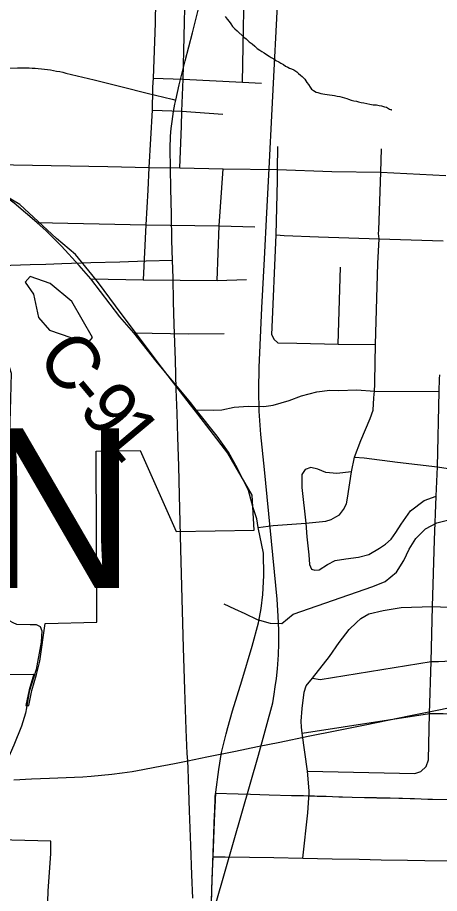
# Model space of a CAD drawing. Extents: x -6.1 to 38, y -7.7 to 22.
# Drawn here: x 5.52 to 5.97, y 16.475 to 17.41 of the extents above; entities that cross this region are included whole.
import ezdxf

# ---------------------------------------------------------------- set-up
doc = ezdxf.new("R2010")
doc.units = 0
for name, color, linetype in [('GM_X_City_Street', 7, 'Continuous'), ('GM_X_Corporation', 7, 'Continuous'), ('GM_X_County_Road', 7, 'Continuous'), ('GM_X_County_Road_Text', 7, 'Continuous'), ('GM_X_Minor_Lake', 7, 'Continuous'), ('GM_X_Minor_River', 7, 'Continuous'), ('GM_X_Rail_Line', 7, 'Continuous'), ('GM_X_Township_Road', 7, 'Continuous'), ('GM_X_Township_Text', 7, 'Continuous'), ('GM_X_US_Route', 7, 'Continuous')]:
    doc.layers.add(name, color=color, linetype=linetype)

msp = doc.modelspace()

# ---------------------------------------------------------------- linework, layer by layer
at = {"layer": 'GM_X_City_Street'}
for p, q in [((5.90593, 17.17394), (5.97422, 17.17178)), ((5.86205, 17.06131), (5.8648, 17.14378))]:
    msp.add_line(p, q, dxfattribs=at)
for points in [[(5.6952, 17.31034), (5.69669, 17.34437), (5.6988, 17.43612), (5.70028, 17.51838), (5.70175, 17.57512)], [(5.75997, 17.34142), (5.7625, 17.47557), (5.76356, 17.5226), (5.76419, 17.5728)], [(5.66809, 17.50632), (5.66822, 17.50045), (5.66695, 17.40448), (5.66463, 17.34543), (5.664, 17.33593), (5.66396, 17.33371)], [(5.66463, 17.34543), (5.69669, 17.34437), (5.75997, 17.34142), (5.78022, 17.34036)], [(5.66396, 17.33371), (5.66356, 17.31151), (5.6602, 17.25029), (5.65894, 17.22583), (5.65683, 17.18892), (5.65388, 17.13007)], [(5.66356, 17.31151), (5.6952, 17.31034), (5.73909, 17.30704)], [(5.6931, 17.24988), (5.69479, 17.29417), (5.6952, 17.31034)], [(5.79119, 17.07122), (5.79604, 17.17816), (5.7973, 17.23616), (5.7973, 17.24798), (5.79772, 17.27245)], [(5.90543, 17.18317), (5.90773, 17.24496), (5.90849, 17.27012)], [(5.73318, 17.12944), (5.73529, 17.18765), (5.7393, 17.24882)], [(5.54061, 17.19124), (5.65683, 17.18892), (5.73529, 17.18765), (5.77325, 17.1866)], [(5.90135, 17.02145), (5.90213, 17.06089), (5.90466, 17.14758), (5.90593, 17.17394), (5.9053, 17.17964), (5.90543, 17.18317)], [(5.79604, 17.17816), (5.80447, 17.17732), (5.84118, 17.17605), (5.90593, 17.17394)], [(5.59798, 17.13113), (5.65388, 17.13007), (5.73318, 17.12944), (5.7644, 17.13049)], [(5.64396, 17.07355), (5.70281, 17.07228), (5.74035, 17.0727)], [(5.79119, 17.07122), (5.79351, 17.06679), (5.79772, 17.06278), (5.81819, 17.06258), (5.86205, 17.06131), (5.90213, 17.06089)], [(5.71061, 16.99128), (5.72939, 16.99086), (5.73803, 16.99138), (5.75132, 16.99402), (5.76608, 16.99508), (5.78276, 16.99463), (5.79262, 16.99608), (5.80993, 17.00113), (5.82303, 17.00605), (5.83928, 17.01048), (5.8532, 17.01217), (5.86238, 17.01196), (5.88209, 17.01259), (5.90087, 17.01132), (5.96984, 17.01069)], [(5.87957, 16.94072), (5.88631, 16.95859), (5.89644, 16.98201), (5.8996, 16.99086), (5.90023, 17.00415), (5.90087, 17.01132), (5.90129, 17.01849), (5.90135, 17.02145)], [(5.7769, 16.86559), (5.79291, 16.86772), (5.82752, 16.87028), (5.84897, 16.87232), (5.85482, 16.87393), (5.85958, 16.87696), (5.86348, 16.87913), (5.86796, 16.8849), (5.87099, 16.89097), (5.87215, 16.89674), (5.87641, 16.92511), (5.87957, 16.94072), (5.8899, 16.94003), (5.92555, 16.93518), (5.96815, 16.93033), (5.99346, 16.92653), (6.01392, 16.92379), (6.02341, 16.92273), (6.03565, 16.92168)], [(5.87641, 16.92511), (5.86079, 16.92337), (5.84885, 16.92447), (5.84033, 16.92801), (5.83288, 16.92959), (5.82682, 16.92767), (5.82346, 16.92231), (5.82346, 16.90839), (5.82752, 16.87028), (5.82873, 16.85566), (5.83084, 16.83647), (5.83158, 16.82598), (5.83379, 16.82087), (5.83735, 16.81982), (5.84202, 16.82044), (5.85067, 16.82592), (5.85915, 16.83032), (5.87041, 16.83205), (5.88398, 16.83393), (5.89509, 16.83682), (5.90635, 16.84332), (5.91285, 16.84779), (5.91892, 16.85313), (5.92365, 16.86009), (5.92934, 16.86916), (5.93947, 16.8835), (5.95402, 16.89426), (5.96667, 16.8989)], [(5.83476, 16.7046), (5.85299, 16.72764), (5.86325, 16.74267), (5.87384, 16.75654), (5.88165, 16.76411), (5.88644, 16.76839), (5.89502, 16.77318), (5.9104, 16.77697), (5.92956, 16.77999), (5.96284, 16.781), (6.00646, 16.77949), (6.0187, 16.77893)], [(5.83476, 16.7046), (5.84282, 16.70334), (5.96158, 16.7225), (5.9694, 16.7225), (6.00946, 16.7247), (6.02805, 16.72531), (6.13288, 16.72383)], [(5.82946, 16.60526), (5.82388, 16.64578), (5.82321, 16.65223), (5.82265, 16.65871), (5.82366, 16.67233), (5.82591, 16.68951), (5.82795, 16.69628), (5.83476, 16.7046)], [(5.82388, 16.64578), (5.95957, 16.66678), (5.97444, 16.66678), (6.01327, 16.66527)]]:
    msp.add_lwpolyline(points, dxfattribs=at)
at = {"layer": 'GM_X_Corporation'}
for points in [[(5.50677, 16.70867), (5.53716, 16.70898), (5.53213, 16.69201), (5.52887, 16.67551), (5.53191, 16.67555), (5.53505, 16.69142), (5.54006, 16.70833), (5.54351, 16.72274), (5.54936, 16.76281), (5.60458, 16.76434), (5.6037, 16.94714), (5.65067, 16.94789), (5.68927, 16.86134), (5.7726, 16.86263), (5.77032, 16.89994), (5.74442, 16.94494), (5.72537, 16.96963), (5.71231, 16.98661), (5.70443, 16.99676), (5.67014, 17.04135), (5.62434, 17.10243), (5.60636, 17.12675), (5.59919, 17.13567), (5.58177, 17.15732), (5.56164, 17.17432), (5.52233, 17.21064), (5.47136, 17.2404)], [(5.98064, 16.57447), (5.96284, 16.57495), (5.95795, 16.57512), (5.95091, 16.57528), (5.94353, 16.57557), (5.93898, 16.5756), (5.93086, 16.57586), (5.92705, 16.57593), (5.91752, 16.57624), (5.91512, 16.57625), (5.90376, 16.57657), (5.90319, 16.57658), (5.90189, 16.57662), (5.89127, 16.5767), (5.89046, 16.5767), (5.87723, 16.57719), (5.86669, 16.57758), (5.86274, 16.57762), (5.8492, 16.57803), (5.83965, 16.57831), (5.83699, 16.57839), (5.83397, 16.57847), (5.83039, 16.57857), (5.82512, 16.57876), (5.81222, 16.57906), (5.78836, 16.57971), (5.76873, 16.58025), (5.7555, 16.5806), (5.73074, 16.58129), (5.7306, 16.57773), (5.72999, 16.56207), (5.72986, 16.5588), (5.72785, 16.50714), (5.72709, 16.47831), (5.72702, 16.47565), (5.72589, 16.45274)], [(5.55226, 16.46594), (5.55266, 16.47692), (5.55533, 16.51714), (5.55542, 16.53037), (5.45844, 16.5328)]]:
    msp.add_lwpolyline(points, dxfattribs=at)
at = {"layer": 'GM_X_County_Road'}
msp.add_line((5.82946, 16.60526), (5.94418, 16.60274), dxfattribs=at)
for points in [[(5.68534, 17.15118), (5.68477, 17.17223), (5.68409, 17.20004), (5.68341, 17.22785), (5.68308, 17.24916), (5.68273, 17.27047), (5.68316, 17.28374), (5.684, 17.29169), (5.68485, 17.29912), (5.68637, 17.31012), (5.68798, 17.31789), (5.68901, 17.32221), (5.69254, 17.33826), (5.69888, 17.36397), (5.70273, 17.37906), (5.70658, 17.39415), (5.71329, 17.42112)], [(5.7044, 16.9989), (5.69944, 17.005), (5.68488, 17.0225), (5.66801, 17.04338), (5.64396, 17.07355), (5.62922, 17.09051), (5.59798, 17.13113), (5.58574, 17.14526), (5.56676, 17.16593), (5.55031, 17.18238), (5.54061, 17.19124), (5.51614, 17.21191), (5.49484, 17.22752), (5.47706, 17.23951), (5.45392, 17.25472), (5.442, 17.26098), (5.43529, 17.2653), (5.42186, 17.27321), (5.41299, 17.27849)], [(5.45392, 17.25472), (5.51551, 17.25304), (5.61633, 17.25114), (5.6602, 17.25029), (5.6931, 17.24988), (5.7393, 17.24882), (5.7973, 17.24798), (5.85552, 17.24591), (5.90773, 17.24496), (5.97716, 17.24175)], [(5.70152, 16.61628), (5.701, 16.62422), (5.69998, 16.64984), (5.69926, 16.67123), (5.69854, 16.69262), (5.69787, 16.71481), (5.69719, 16.737), (5.69644, 16.76326), (5.69567, 16.7895), (5.69499, 16.81588), (5.69432, 16.84226), (5.69351, 16.87126), (5.69271, 16.90025), (5.69195, 16.93107), (5.69119, 16.96189), (5.6903, 16.98754), (5.68941, 17.0132), (5.68843, 17.04425), (5.68782, 17.06326), (5.68721, 17.08227), (5.68654, 17.10705), (5.68586, 17.13181), (5.68534, 17.15118)], [(5.94418, 16.60274), (5.95049, 16.60501), (5.95604, 16.61005), (5.95855, 16.61736), (5.95957, 16.66678), (5.96158, 16.7225), (5.96284, 16.781), (5.96498, 16.85208), (5.96667, 16.8989), (5.96815, 16.93033), (5.96984, 17.01069), (5.97047, 17.0244), (5.97082, 17.02876)], [(5.74437, 16.65175), (5.74953, 16.6698), (5.75937, 16.70158), (5.77021, 16.73864), (5.77701, 16.76386), (5.78004, 16.77899), (5.7818, 16.79386), (5.78281, 16.81429), (5.78231, 16.83798), (5.7769, 16.86559), (5.77533, 16.87464), (5.7714, 16.88644), (5.76628, 16.90492), (5.75469, 16.92843), (5.74499, 16.94594), (5.73297, 16.96323), (5.71061, 16.99128), (5.7044, 16.9989)], [(5.73111, 16.57374), (5.73163, 16.58282), (5.73466, 16.60702), (5.7378, 16.62503), (5.74247, 16.6451), (5.74437, 16.65175)], [(5.707, 16.46973), (5.70607, 16.49462), (5.70495, 16.52567), (5.70428, 16.54426), (5.70362, 16.56284), (5.70277, 16.58538), (5.70192, 16.60791), (5.70152, 16.61628)], [(5.72684, 16.46381), (5.7276, 16.49053), (5.72886, 16.51374), (5.73037, 16.56063), (5.73111, 16.57374)]]:
    msp.add_lwpolyline(points, dxfattribs=at)
at = {"layer": 'GM_X_Minor_Lake'}
for points in [[(5.59507, 17.0625), (5.59996, 17.06859), (5.57785, 17.10687), (5.55467, 17.12617), (5.53345, 17.13371), (5.52818, 17.12763)], [(5.52818, 17.12763), (5.53694, 17.11474), (5.54234, 17.08971), (5.55414, 17.07645), (5.57688, 17.06853), (5.59507, 17.0625)]]:
    msp.add_lwpolyline(points, dxfattribs=at)
at = {"layer": 'GM_X_Minor_River'}
for points in [[(5.74138, 17.41133), (5.7437, 17.40871), (5.74565, 17.40609), (5.7476, 17.40346), (5.74954, 17.40083), (5.75187, 17.39821), (5.75419, 17.39597), (5.76152, 17.38926), (5.76384, 17.3874), (5.76731, 17.38442), (5.77039, 17.38219), (5.77309, 17.37958), (5.77579, 17.37735), (5.77848, 17.3755), (5.78079, 17.37402), (5.78309, 17.37254), (5.78578, 17.37069), (5.78847, 17.36921), (5.79077, 17.36773), (5.79346, 17.36626), (5.79577, 17.3644), (5.79884, 17.36293), (5.80114, 17.36145), (5.80383, 17.35998), (5.80613, 17.3585), (5.80843, 17.3574), (5.81035, 17.3563), (5.81226, 17.35557)], [(5.81226, 17.35557), (5.81494, 17.35448), (5.81802, 17.35225), (5.81995, 17.35038), (5.82188, 17.3489), (5.8238, 17.34741), (5.82651, 17.34442), (5.82885, 17.34104), (5.83041, 17.33879), (5.83237, 17.33578), (5.83354, 17.3339), (5.83584, 17.33242), (5.83854, 17.33057), (5.84044, 17.33022), (5.8435, 17.32913), (5.84807, 17.32846), (5.85035, 17.32812), (5.85835, 17.32712), (5.86102, 17.32641), (5.86406, 17.32608), (5.86636, 17.32536), (5.86903, 17.32465), (5.87132, 17.32393), (5.87323, 17.3232), (5.87591, 17.32211), (5.87896, 17.32141), (5.88162, 17.32107), (5.88392, 17.32035), (5.88659, 17.31964), (5.88963, 17.31932), (5.89268, 17.31861), (5.89611, 17.31791), (5.89954, 17.31721), (5.90297, 17.3169), (5.90602, 17.31619), (5.9083, 17.31585), (5.91174, 17.31477), (5.91365, 17.31443), (5.9171, 17.31259), (5.91901, 17.31186), (5.91939, 17.31187), (5.91901, 17.31186)], [(5.74025, 16.78404), (5.75161, 16.77877), (5.7626, 16.7735), (5.77585, 16.7671), (5.78948, 16.76335), (5.80196, 16.76301), (5.81403, 16.7729), (5.89904, 16.80236), (5.91226, 16.80771), (5.92433, 16.81798), (5.93223, 16.83013), (5.93787, 16.84228), (5.94502, 16.85368), (5.95557, 16.86394), (5.96766, 16.87043), (5.98164, 16.87426)]]:
    msp.add_lwpolyline(points, dxfattribs=at)
at = {"layer": 'GM_X_Rail_Line'}
msp.add_lwpolyline([(5.70525, 16.37213), (5.77707, 16.62218), (5.7924, 16.67838), (5.79376, 16.68741), (5.79503, 16.69527), (5.79629, 16.7044), (5.79736, 16.71449), (5.79842, 16.72963), (5.79891, 16.74167), (5.79881, 16.75594), (5.79803, 16.77098), (5.79697, 16.78884), (5.78338, 16.92754), (5.77979, 16.96491), (5.77785, 16.98976), (5.77736, 17.01277), (5.77775, 17.03664), (5.78076, 17.10012), (5.78367, 17.15244), (5.7859, 17.20165), (5.78843, 17.24921), (5.79173, 17.3125), (5.79842, 17.4447)], dxfattribs=at)
at = {"layer": 'GM_X_Township_Road'}
msp.add_line((5.83106, 16.58417), (5.82946, 16.60526), dxfattribs=at)
for points in [[(5.49627, 17.35586), (5.51992, 17.35657), (5.5255, 17.35665), (5.53214, 17.35654), (5.53546, 17.3564), (5.53873, 17.35619), (5.54204, 17.35594), (5.54531, 17.35562), (5.54862, 17.35525), (5.55189, 17.35482), (5.55517, 17.35433), (5.55844, 17.35379), (5.56165, 17.35318), (5.56492, 17.35253), (5.56815, 17.35182), (5.57137, 17.35105), (5.60154, 17.34363), (5.63171, 17.33621), (5.65832, 17.32967), (5.68493, 17.32313), (5.68901, 17.32221)], [(5.50233, 17.14558), (5.53338, 17.14652), (5.55021, 17.14703), (5.56705, 17.14753), (5.5981, 17.14849), (5.62916, 17.14944), (5.65725, 17.15031), (5.68534, 17.15118)], [(5.50695, 17.041), (5.51106, 17.03726), (5.51322, 17.03055), (5.51243, 17.00344), (5.51133, 16.96582), (5.5101, 16.89099), (5.50938, 16.81689), (5.50843, 16.77661), (5.50915, 16.77061), (5.51106, 16.7663), (5.5149, 16.76413), (5.51894, 16.76217), (5.53321, 16.76179), (5.53987, 16.76179), (5.54391, 16.75982), (5.54583, 16.75503), (5.54511, 16.74303), (5.5396, 16.71378), (5.53245, 16.69051), (5.52936, 16.67307)], [(5.52936, 16.67307), (5.52833, 16.66726), (5.52397, 16.65323), (5.5161, 16.63297), (5.50958, 16.61832)], [(5.82441, 16.51217), (5.82971, 16.5607), (5.83122, 16.58206), (5.83106, 16.58417)], [(5.72886, 16.51374), (5.74141, 16.51384), (5.79341, 16.51291), (5.82441, 16.51217), (5.8558, 16.51161), (5.88449, 16.51121), (5.90816, 16.51068), (5.9362, 16.50999), (5.95464, 16.50991), (5.98578, 16.50957), (6.00152, 16.50918), (6.01735, 16.50697), (6.04428, 16.49936), (6.06805, 16.49304), (6.09534, 16.48895), (6.13566, 16.48501)]]:
    msp.add_lwpolyline(points, dxfattribs=at)
at = {"layer": 'GM_X_US_Route'}
msp.add_lwpolyline([(5.51595, 16.59611), (5.5349, 16.59692), (5.55387, 16.59773), (5.57178, 16.59847), (5.5897, 16.59921), (5.5985, 16.59979), (5.60946, 16.60079), (5.62049, 16.602), (5.6316, 16.60346), (5.6423, 16.60504), (5.65375, 16.60697), (5.66629, 16.60934), (5.6875, 16.61355), (5.70152, 16.61628), (5.72195, 16.62053), (5.7524, 16.62672), (5.77611, 16.63153), (5.79982, 16.63635), (5.83027, 16.64253), (5.86071, 16.64871), (5.89116, 16.65489), (5.9152, 16.65977), (5.93924, 16.66466), (5.96968, 16.67086), (5.99715, 16.67645)], dxfattribs=at)

# ---------------------------------------------------------------- texts
at = {"layer": 'GM_X_County_Road_Text'}
for s, rotation, p in [('C', 308.29468, (5.5388, 17.0468)), ('-', 309.7016, (5.56868, 17.00899)), ('9', 309.87931, (5.58371, 16.99089)), ('1', 309.95243, (5.6062, 16.96397))]:
    msp.add_text(s, height=0.05682, rotation=rotation, dxfattribs=at).set_placement(p)
at = {"layer": 'GM_X_Township_Text'}
msp.add_text('MUNSON', height=0.170455, rotation=0.00001, dxfattribs=at).set_placement((4.63363, 16.80102))

doc.saveas('drawing.dxf')
